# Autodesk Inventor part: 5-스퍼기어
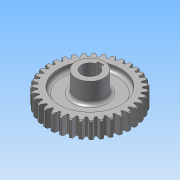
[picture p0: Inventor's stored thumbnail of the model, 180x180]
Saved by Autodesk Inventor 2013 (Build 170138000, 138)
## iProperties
Created: 2013-08
Part Number: 5-스퍼기어
Material: 강
Document SubType Name: Modeling
Designer: 한국산업디자인학원
Categories: <?xml version="1.0" encoding="UTF-16"?> <MemberInstance><Categories><FamilyTemplate><FamilyTemplateParameter ValueType="xs:double" Id="1" ObjectReferenceKey="da
Density: 1 g/cm^3
CustomPartVersion: 1
Author: 한국산업디자인학원
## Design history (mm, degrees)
sketch "Sketch1"
  geometry: C1 r 37 at (0, 0)
  constraints: 1 centre point
  dimensions: "d0" = 74 diameter of C1 (= da_da)
extrude "Extrusion1" new body sketch "Sketch1" distance "d1" = 15 (= da_b); taper "d2" = 0 deg
chamfer "모따기1" distance "d49" = 1; stored, may be unused: second distance "d50" = 2, angle "d51" = 45 deg
node "작업 평면11"
sketch "스케치3"
  geometry: C1 r 12.5 at (0, 0); 1 further point
  constraints: 1 centre point, 1 coincident
  dimensions: "d53" = 25 diameter of C1
extrude "돌출2" join sketch "스케치3" distance "d55" = 31; taper "d56" = 0 deg
sketch "스케치4"
  geometry: L1 (-2.5, 7.071)-(-2.5, 9.8); L2 (-2.5, 9.8)-(2.5, 9.8); L3 (2.5, 9.8)-(2.5, 7.071); C1 r 12.5 at (0, 0) reference; A1 r 7.5 centre (0, 0) between (-2.5, 7.071) and (2.5, 7.071)
  constraints: 6 end point, 2 parallel, 2 point on circle, 1 centre point, 1 coincident, 1 perpendicular, 1 vertical
  dimensions: "d57" = 15 diameter of A1; "d59" = 5 distance of L1.end L2.end; "d60" = 17.3 dimension on A1 L2
extrude "돌출3" cut sketch "스케치4" distance "d61" = 31; taper "d62" = 0 deg
workplane "Work Plane2"
feature "피치 지름" dims "d4" = 10, "d5" = 0
workplane "Work Plane8"
workplane "Work Plane9"
feature "스퍼 기어" dims "da_b" = 15, "da_d" = 70, "da_aw" = 70, "da_da" = 74, "da_df" = 65, "da_dw" = 70, angle "da_beta" = 0 deg, "da_lefttooth" = 0, "da_righttooth" = 0
sketch "스케치5"
  geometry: C1 r 12.5 at (0, 0) reference; C2 r 27.5 at (0, 0); C3 r 12.5 at (0, 0)
  constraints: 2 centre point, 2 coincident
  dimensions: "d63" = 55 diameter of C2; "d65" = 25 diameter of C3
extrude "돌출4" cut sketch "스케치5" distance "d66" = 5; taper "d67" = 0 deg
sketch "스케치7"
  geometry: C1 r 12.5 at (0, 0) reference; C2 r 27.5 at (0, 0) reference; C3 r 12.5 at (0, 0) reference
extrude "돌출5" cut sketch "스케치7" distance "d68" = 5; taper "d69" = 0 deg
fillet "모깎기1" dims "d70" = 3
sketch "스케치8"
  geometry: 1 further point
body "Solid1"
sketch "Sketch2"
  geometry: C1 r 37 at (0, 0) reference; C2 r 35 at (0, 0)
  constraints: 1 centre point, 1 coincident
  dimensions: "d3" = 70 diameter of C2 (= da_dw)
body "Srf1"
other parameters: "d17" = 0, "d34" = 0.8976 (computed from da_z), "d39" = 0, "d41" = 0, "d47" = 0, "d48" = 0, "d52" = 3
